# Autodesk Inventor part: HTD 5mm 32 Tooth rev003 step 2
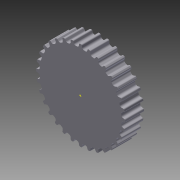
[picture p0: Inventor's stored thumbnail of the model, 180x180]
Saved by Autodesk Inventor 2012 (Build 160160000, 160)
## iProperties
Created: 2011-12
Part Number: HTD 5mm 32 Tooth rev003 step 2
Document SubType Name: Modeling
Designer: Alex
Density: 2.71 g/cm^3
Material: Aluminum-6061
Mass: 50.5223 g
Surface Area: 59.5299 cm^2
Volume: 18.6429 cm^3
Author: Alex
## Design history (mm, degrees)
sketch "Sketch2"
  geometry: C1 r 24.892 at (0, 0); 1 further point
  constraints: 1 centre point, 1 coincident
  dimensions: "d122" = 49.784 diameter of C1
extrude "Extrusion1" new body sketch "Sketch2" distance "d123" = 10.5664; taper "d124" = 0 deg
sketch "Sketch1"
  geometry: L1 (-24.849, 24.935)-(24.935, 24.849); L2 (24.935, 24.849)-(24.849, -24.935); L3 (24.849, -24.935)-(-24.935, -24.849); L4 (-24.935, -24.849)-(-24.849, 24.935); L5 (-28.232, 0.025)-(27.326, -0.024); L6 (1.836, 22.79)-(2.645, 22.71); L7 (0.806, 24.44)-(0.932, 23.642); L8 (3.977, 24.128)-(3.698, 23.37); L9 (-3.977, 24.128)-(-3.698, 23.37); L10 (-2.645, 22.71)-(-1.836, 22.79); L11 (-0.806, 24.44)-(-0.932, 23.642); L12 (-8.608, 22.888)-(-8.186, 22.199); L13 (-7.025, 21.758)-(-6.247, 21.994); L14 (-5.559, 23.813)-(-5.527, 23.006); L15 (-12.908, 20.769)-(-12.36, 20.176); L16 (-11.135, 19.969)-(-10.418, 20.352); L17 (-10.098, 22.271)-(-9.909, 21.486); L18 (-16.712, 17.852)-(-16.058, 17.377); L19 (-14.816, 17.413)-(-14.188, 17.929); L20 (-14.249, 19.873)-(-13.91, 19.14); L21 (-19.873, 14.249)-(-19.14, 13.91); L22 (-17.929, 14.188)-(-17.413, 14.816); L23 (-17.852, 16.712)-(-17.377, 16.058); L24 (-22.271, 10.098)-(-21.486, 9.909); L25 (-20.352, 10.418)-(-19.969, 11.135); L26 (-20.769, 12.908)-(-20.176, 12.36); L27 (-23.813, 5.559)-(-23.006, 5.527); L28 (-21.994, 6.247)-(-21.758, 7.025); L29 (-22.888, 8.608)-(-22.199, 8.186); L30 (-24.44, 0.806)-(-23.642, 0.932); L31 (-22.79, 1.836)-(-22.71, 2.645); L32 (-24.128, 3.977)-(-23.37, 3.698); L33 (-24.128, -3.977)-(-23.37, -3.698); L34 (-22.71, -2.645)-(-22.79, -1.836); L35 (-24.44, -0.806)-(-23.642, -0.932); L36 (-22.888, -8.608)-(-22.199, -8.186); L37 (-21.758, -7.025)-(-21.994, -6.247); L38 (-23.813, -5.559)-(-23.006, -5.527); L39 (-20.769, -12.908)-(-20.176, -12.36); L40 (-19.969, -11.135)-(-20.352, -10.418); L41 (-22.271, -10.098)-(-21.486, -9.909); L42 (-17.852, -16.712)-(-17.377, -16.058); L43 (-17.413, -14.816)-(-17.929, -14.188); L44 (-19.873, -14.249)-(-19.14, -13.91); L45 (-14.249, -19.873)-(-13.91, -19.14); L46 (-14.188, -17.929)-(-14.816, -17.413); L47 (-16.712, -17.852)-(-16.058, -17.377); L48 (-10.098, -22.271)-(-9.909, -21.486); L49 (-10.418, -20.352)-(-11.135, -19.969); L50 (-12.908, -20.769)-(-12.36, -20.176); L51 (-5.559, -23.813)-(-5.527, -23.006); L52 (-6.247, -21.994)-(-7.025, -21.758); L53 (-8.608, -22.888)-(-8.186, -22.199); L54 (-0.806, -24.44)-(-0.932, -23.642); L55 (-1.836, -22.79)-(-2.645, -22.71); L56 (-3.977, -24.128)-(-3.698, -23.37); L57 (3.977, -24.128)-(3.698, -23.37); L58 (2.645, -22.71)-(1.836, -22.79); L59 (0.806, -24.44)-(0.932, -23.642); L60 (8.608, -22.888)-(8.186, -22.199); L61 (7.025, -21.758)-(6.247, -21.994); L62 (5.559, -23.813)-(5.527, -23.006); L63 (12.908, -20.769)-(12.36, -20.176); L64 (11.135, -19.969)-(10.418, -20.352)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; A1 r 0.533 centre (0.279, 24.357) between (0.806, 24.44) and (0.286, 24.89); A2 r 0.533 centre (4.478, 23.943) between (4.576, 24.468) and (3.977, 24.128); A3 r 1.016 centre (2.745, 23.721) between (2.645, 22.71) and (3.698, 23.37); A4 r 1.016 centre (1.936, 23.801) between (0.932, 23.642) and (1.836, 22.79); A5 r 24.892 centre (0, 0) between (4.576, 24.468) and (0.286, 24.89); A6 r 24.892 centre (0, 0) between (-24.892, 0.043) and (-24.892, 0.022); A7 r 24.892 centre (0, 0) between (24.892, -0.043) and (24.892, -0.022); A8 r 0.533 centre (-4.478, 23.943) between (-3.977, 24.128) and (-4.576, 24.468); A9 r 1.016 centre (-2.745, 23.721) between (-3.698, 23.37) and (-2.645, 22.71); A10 r 1.016 centre (-1.936, 23.801) between (-1.836, 22.79) and (-0.932, 23.642); A11 r 0.533 centre (-0.279, 24.357) between (-0.286, 24.89) and (-0.806, 24.44); A12 r 24.892 centre (0, 0) between (-0.286, 24.89) and (-4.576, 24.468); A13 r 0.533 centre (-9.063, 22.61) between (-8.608, 22.888) and (-9.261, 23.105); A14 r 1.016 centre (-7.32, 22.73) between (-8.186, 22.199) and (-7.025, 21.758); A15 r 1.016 centre (-6.542, 22.966) between (-6.247, 21.994) and (-5.527, 23.006); A16 r 0.533 centre (-5.026, 23.834) between (-5.136, 24.356) and (-5.559, 23.813); A17 r 24.892 centre (0, 0) between (-5.136, 24.356) and (-9.261, 23.105); A18 r 0.533 centre (-13.3, 20.407) between (-12.908, 20.769) and (-13.591, 20.854); A19 r 1.016 centre (-11.613, 20.865) between (-12.36, 20.176) and (-11.135, 19.969); A20 r 1.016 centre (-10.897, 21.248) between (-10.418, 20.352) and (-9.909, 21.486); A21 r 0.533 centre (-9.579, 22.396) between (-9.789, 22.886) and (-10.098, 22.271); A22 r 24.892 centre (0, 0) between (-9.789, 22.886) and (-13.591, 20.854); A23 r 0.533 centre (-17.025, 17.421) between (-16.712, 17.852) and (-17.398, 17.802); A24 r 1.016 centre (-15.461, 18.199) between (-16.058, 17.377) and (-14.816, 17.413); A25 r 1.016 centre (-14.833, 18.714) between (-14.188, 17.929) and (-13.91, 19.14); A26 r 0.533 centre (-13.764, 20.097) between (-14.066, 20.537) and (-14.249, 19.873); A27 r 24.892 centre (0, 0) between (-14.066, 20.537) and (-17.398, 17.802); A28 r 0.533 centre (-20.097, 13.764) between (-19.873, 14.249) and (-20.537, 14.066); A29 r 1.016 centre (-18.714, 14.833) between (-19.14, 13.91) and (-17.929, 14.188); A30 r 1.016 centre (-18.199, 15.461) between (-17.413, 14.816) and (-17.377, 16.058); A31 r 0.533 centre (-17.421, 17.025) between (-17.802, 17.398) and (-17.852, 16.712); A32 r 24.892 centre (0, 0) between (-17.802, 17.398) and (-20.537, 14.066); A33 r 0.533 centre (-22.396, 9.579) between (-22.271, 10.098) and (-22.886, 9.789); A34 r 1.016 centre (-21.248, 10.897) between (-21.486, 9.909) and (-20.352, 10.418); A35 r 1.016 centre (-20.865, 11.613) between (-19.969, 11.135) and (-20.176, 12.36); A36 r 0.533 centre (-20.407, 13.3) between (-20.854, 13.591) and (-20.769, 12.908); A37 r 24.892 centre (0, 0) between (-20.854, 13.591) and (-22.886, 9.789); A38 r 0.533 centre (-23.834, 5.026) between (-23.813, 5.559) and (-24.356, 5.136); A39 r 1.016 centre (-22.966, 6.542) between (-23.006, 5.527) and (-21.994, 6.247); A40 r 1.016 centre (-22.73, 7.32) between (-21.758, 7.025) and (-22.199, 8.186); A41 r 0.533 centre (-22.61, 9.063) between (-23.105, 9.261) and (-22.888, 8.608); A42 r 24.892 centre (0, 0) between (-23.105, 9.261) and (-24.356, 5.136); A43 r 0.533 centre (-24.357, 0.279) between (-24.44, 0.806) and (-24.89, 0.286); A44 r 1.016 centre (-23.801, 1.936) between (-23.642, 0.932) and (-22.79, 1.836); A45 r 1.016 centre (-23.721, 2.745) between (-22.71, 2.645) and (-23.37, 3.698); A46 r 0.533 centre (-23.943, 4.478) between (-24.468, 4.576) and (-24.128, 3.977); A47 r 24.892 centre (0, 0) between (-24.468, 4.576) and (-24.89, 0.286); A48 r 0.533 centre (-23.943, -4.478) between (-24.128, -3.977) and (-24.468, -4.576); A49 r 1.016 centre (-23.721, -2.745) between (-23.37, -3.698) and (-22.71, -2.645); A50 r 1.016 centre (-23.801, -1.936) between (-22.79, -1.836) and (-23.642, -0.932); A51 r 0.533 centre (-24.357, -0.279) between (-24.89, -0.286) and (-24.44, -0.806); A52 r 24.892 centre (0, 0) between (-24.89, -0.286) and (-24.468, -4.576); A53 r 0.533 centre (-22.61, -9.063) between (-22.888, -8.608) and (-23.105, -9.261); A54 r 1.016 centre (-22.73, -7.32) between (-22.199, -8.186) and (-21.758, -7.025); A55 r 1.016 centre (-22.966, -6.542) between (-21.994, -6.247) and (-23.006, -5.527); A56 r 0.533 centre (-23.834, -5.026) between (-24.356, -5.136) and (-23.813, -5.559); A57 r 24.892 centre (0, 0) between (-24.356, -5.136) and (-23.105, -9.261); A58 r 0.533 centre (-20.407, -13.3) between (-20.769, -12.908) and (-20.854, -13.591); A59 r 1.016 centre (-20.865, -11.613) between (-20.176, -12.36) and (-19.969, -11.135); A60 r 1.016 centre (-21.248, -10.897) between (-20.352, -10.418) and (-21.486, -9.909); A61 r 0.533 centre (-22.396, -9.579) between (-22.886, -9.789) and (-22.271, -10.098); A62 r 24.892 centre (0, 0) between (-22.886, -9.789) and (-20.854, -13.591); A63 r 0.533 centre (-17.421, -17.025) between (-17.852, -16.712) and (-17.802, -17.398); A64 r 1.016 centre (-18.199, -15.461) between (-17.377, -16.058) and (-17.413, -14.816)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; 3 further points; 1 other entity
  constraints: 324 point on circle, 194 end point, 162 centre point, 3 point on line, 3 tangent, 2 midpoint, 1 coincident, 675 other
  dimensions: "d14" = 24.892 distance from line of L4 point (0, 0); "d17" = 24.892 distance from line of point (0, 0) L1; "d19" = 89.95 deg angle of L4 L5; "d127" = 360 deg dimension on point (0, 0) A1.centre (derived)
extrude "Extrusion2" cut sketch "Sketch1" stored distance "d160" = 10.5664; taper "d161" = 0 deg
body "Solid1"
node "Image1"
other parameters: "d0" = 49.784, "d47" = 2.032
